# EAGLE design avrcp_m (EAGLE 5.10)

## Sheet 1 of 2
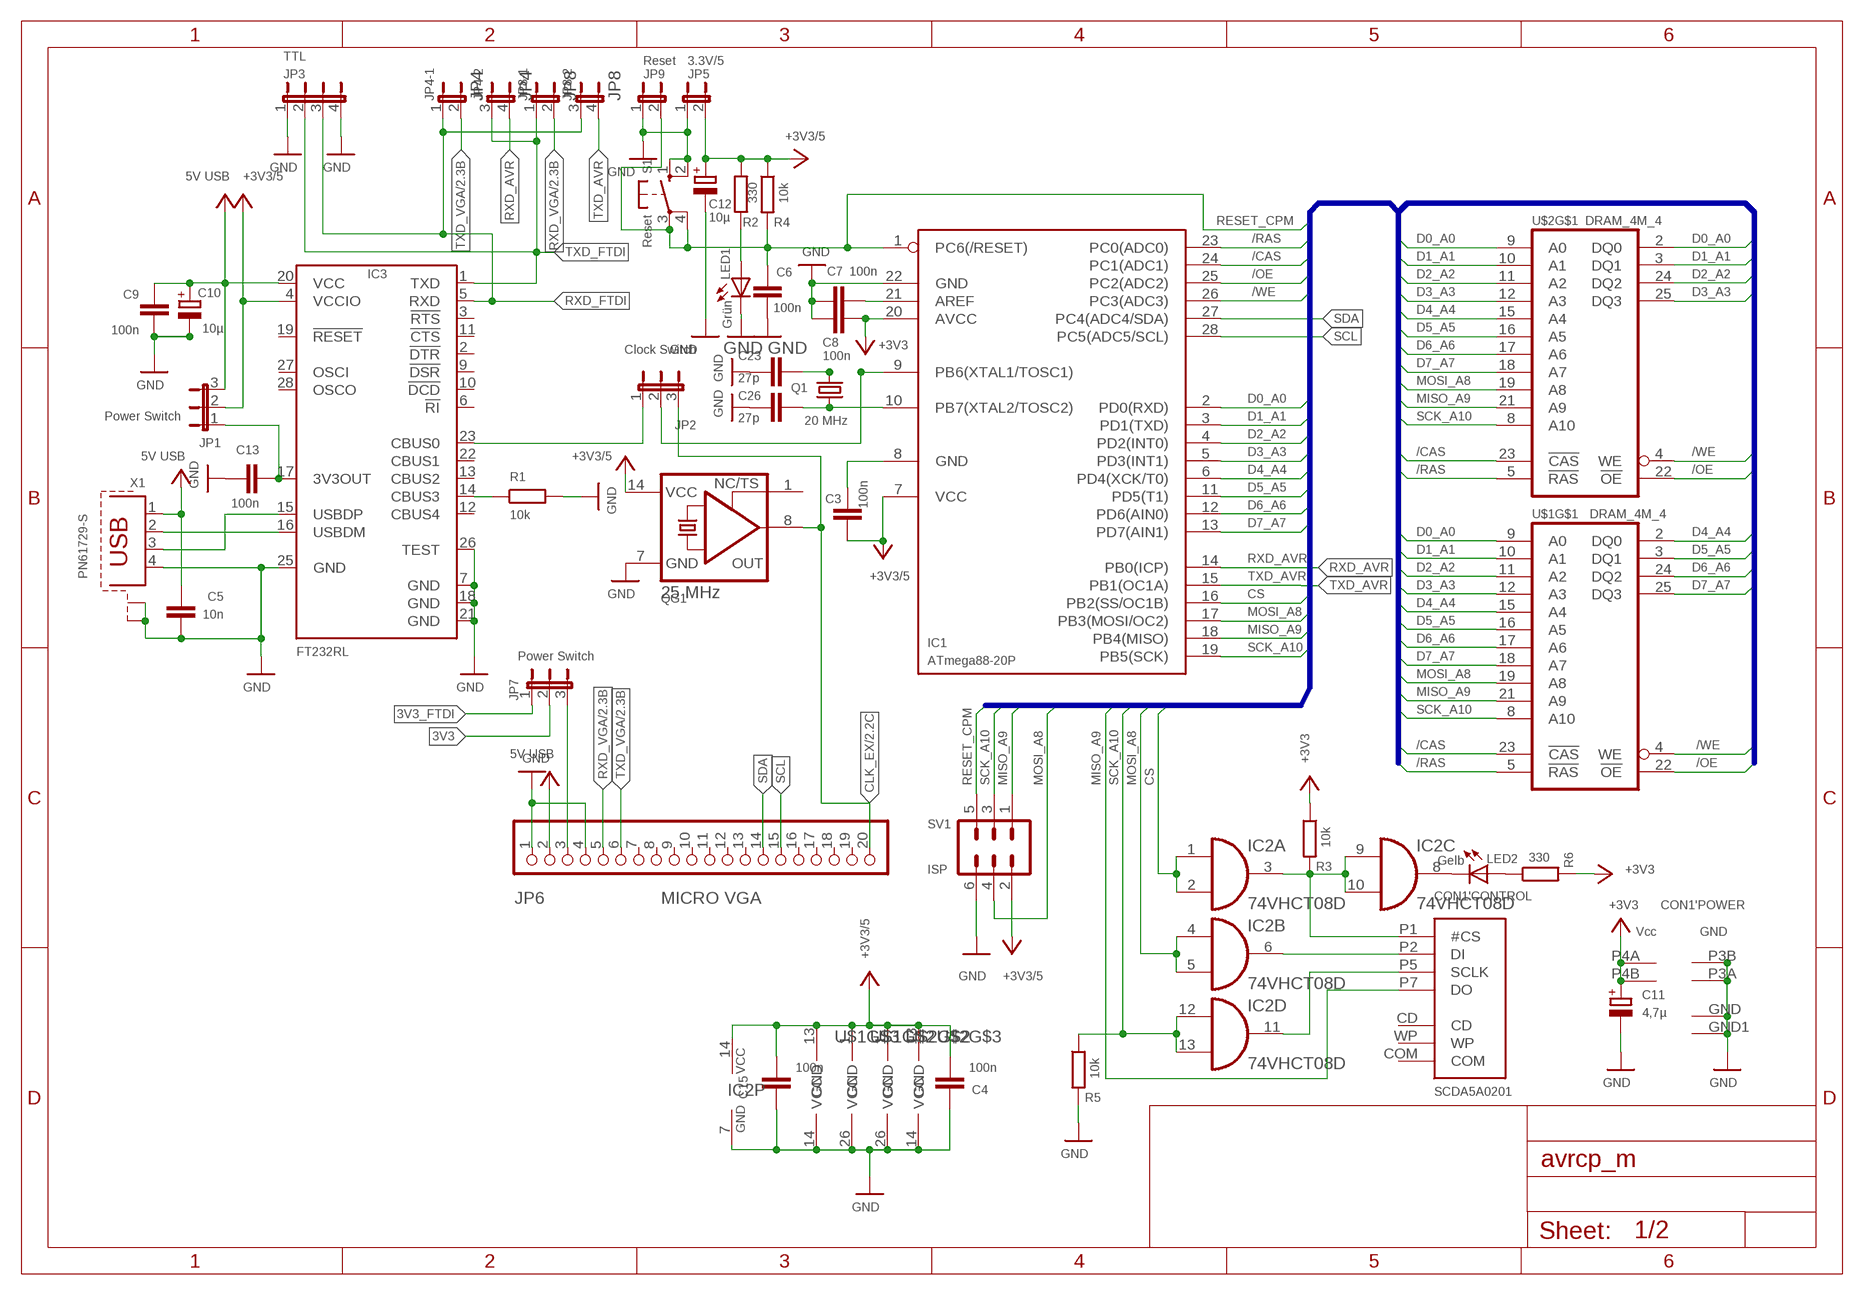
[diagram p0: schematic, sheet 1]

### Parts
C3  100n  C-EU025-024X044  [C025-024X044]
C4  100n  C-EU025-024X044  [C025-024X044]
C5  10n  C-EU025-024X044  [C025-024X044]
C6  100n  C-EU025-024X044  [C025-024X044]
C7  100n  C-EU025-024X044  [C025-024X044]
C8  100n  C-EU025-024X044  [C025-024X044]
C9  100n  C-EU025-024X044  [C025-024X044]
C10  10µ  CPOL-EUE2-5  [E2-5]
C11  4,7µ  CPOL-EUE2-4  [E2-4]
C12  10µ  CPOL-EUE2-4  [E2-4]
C13  100n  C-EU025-024X044  [C025-024X044]
C15  100n  C-EU025-024X044  [C025-024X044]
C23  27p  C-EU025-024X044  [C025-024X044]
C26  27p  C-EU025-024X044  [C025-024X044]
CON1  SCDA5A0201  [SCDA5A0201]
IC1  ATmega88-20P  MEGA8-P  [DIL28-3]
IC2  74VHCT08D  74S08D  [SO14]
IC3  FT232RL  [SSOP28]
JP1  Power Switch  JP2E  [JP2]
JP2  Clock Switch  JP2E  [JP2]
JP3  TTL  JP4E  [JP4]
JP4  JP4  JP2QE  [JP2Q]
JP5  3.3V/5  JP1E  [JP1]
JP6  MICRO VGA  PINHD-1X20  [1X20]
JP7  Power Switch  JP2E  [JP2]
JP8  JP8  JP2QE  [JP2Q]
JP9  Reset  JP1E  [JP1]
LED1  Grün  LED3MM  [LED3MM]
LED2  Gelb  LED3MM  [LED3MM]
Q1  20 MHz  CRYSTALHC49S  [HC49/S]
QG1  25 MHz  XO-14  [DIL14S]
R1  10k  R-EU_0207/7  [0207/7]
R2  330  R-EU_0207/7  [0207/7]
R3  10k  R-EU_M1206  [M1206]
R4  10k  R-EU_0207/7  [0207/7]
R5  10k  R-EU_M1206  [M1206]
R6  330  R-EU_0204/7  [0204/7]
S1  Reset  10-XX  [B3F-10XX]
SV1  ISP  ML6  [ML6]
U$1  DRAM_4M_4  [SOJ26-24]
U$2  DRAM_4M_4  [SOJ26-24]
X1  PN61729-S  [PN61729-S]

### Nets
3V3: C11.+ CON1.P4A('POWER:VCC) CON1.P4B('POWER:VCC1) JP7.2 R3.1 R6.2 ; supply symbol labelled +3V3
3V3_FTDI: C13.2 IC3.17(3V3OUT) JP1.1 JP7.1
3V3_VGA: JP6.3 JP7.3 ; also sheet 2
5V_USB: C5.2 C9.2 C10.+ IC3.20(VCC) JP1.3 JP6.2 X1.1 ; supply symbol labelled 5V USB ; also sheet 2
+3V3/5: C3.1 C4.2 C8.1 C12.+ C15.2 IC1.7(VCC) IC1.20(AVCC) IC2.14(P:VCC) IC3.4(VCCIO) JP1.2 JP5.2 QG1.14(VCC) R2.2 R4.1 SV1.2 U$1.1(VCC) U$1.13(VCC) U$2.1(VCC) U$2.13(VCC) ; supply symbol labelled +3V3
/CAS: IC1.24(PC1(ADC1)) U$1.23(!CAS) U$2.23(!CAS)
/OE: IC1.25(PC2(ADC2)) U$1.22(!OE) U$2.22(!OE)
/RAS: IC1.23(PC0(ADC0)) U$1.5(!RAS) U$2.5(!RAS)
/WE: IC1.26(PC3(ADC3)) U$1.4(WE) U$2.4(WE)
CLK_EX: JP2.3 JP6.20 QG1.8(OUT) ; also sheet 2
CS: IC1.16(PB2(SS/OC1B)) IC2.1(A:I0) IC2.2(A:I1)
CS_MMC: CON1.P1('CONTROL:#CS) IC2.3(A:O) IC2.9(C:I0) IC2.10(C:I1) R3.2
D0_A0: IC1.2(PD0(RXD)) U$1.9(A0) U$2.2(DQ0) U$2.9(A0)
D1_A1: IC1.3(PD1(TXD)) U$1.10(A1) U$2.3(DQ1) U$2.10(A1)
D2_A2: IC1.4(PD2(INT0)) U$1.11(A2) U$2.11(A2) U$2.24(DQ2)
D3_A3: IC1.5(PD3(INT1)) U$1.12(A3) U$2.12(A3) U$2.25(DQ3)
D4_A4: IC1.6(PD4(XCK/T0)) U$1.2(DQ0) U$1.15(A4) U$2.15(A4)
D5_A5: IC1.11(PD5(T1)) U$1.3(DQ1) U$1.16(A5) U$2.16(A5)
D6_A6: IC1.12(PD6(AIN0)) U$1.17(A6) U$1.24(DQ2) U$2.17(A6)
D7_A7: IC1.13(PD7(AIN1)) U$1.18(A7) U$1.25(DQ3) U$2.18(A7)
GND: C4.1 C5.1 C6.1 C7.2 C8.2 C9.1 C10.- C11.- C12.- C13.1 C15.1 C23.2 C26.2 CON1.GND1('POWER:GND) CON1.GND('POWER:GND) CON1.P3A('POWER:GND) CON1.P3B('POWER:GND) IC1.22(GND) IC2.7(P:GND) IC3.7(GND) IC3.18(GND) IC3.21(GND) IC3.25(GND) IC3.26(TEST) JP3.1 JP3.4 JP5.1 JP6.1 JP6.4 JP9.1 LED1.K(C) QG1.7(GND) R1.2 R5.2 S1.1(S) S1.2(S1) SV1.6 U$1.14(GND) U$1.26(GND) U$2.14(GND) U$2.26(GND) X1.4 X1.S1 X1.S2 ; also sheet 2
MISO_A9: CON1.P7('CONTROL:DO) IC1.18(PB4(MISO)) SV1.1 U$1.21(A9) U$2.21(A9)
MOSI_A8: IC1.17(PB3(MOSI/OC2)) IC2.4(B:I0) IC2.5(B:I1) SV1.4 U$1.19(A8) U$2.19(A8)
MOSI_MMC: CON1.P2('CONTROL:DI) IC2.6(B:O)
N$1: IC3.14(CBUS3) R1.1
N$3: C7.1 IC1.21(AREF)
N$4: IC1.9(PB6(XTAL1/TOSC1)) JP2.2
N$7: LED1.A R2.1
N$8: IC3.23(CBUS0) JP2.1
N$9: IC3.16(USBDM) X1.2
N$10: IC3.15(USBDP) X1.3
N$12: IC2.8(C:O) LED2.K(C)
N$13: LED2.A R6.1
N$14: C3.2 IC1.8(GND)
N$23: C26.1 IC1.10(PB7(XTAL2/TOSC2)) Q1.1
N$24: C23.1 Q1.2
RESET_CPM: C6.2 IC1.1(PC6(/RESET)) JP9.2 R4.2 S1.3(P) S1.4(P1) SV1.5
RXD_AVR: IC1.14(PB0(ICP)) JP4.4
RXD_FTDI: IC3.5(RXD) JP3.3 JP4.1 JP8.3
RXD_VGA: JP6.5 JP8.2 ; also sheet 2
SCK_A10: IC1.19(PB5(SCK)) IC2.12(D:I0) IC2.13(D:I1) R5.1 SV1.3 U$1.8(A10) U$2.8(A10)
SCK_MMC: CON1.P5('CONTROL:SCLK) IC2.11(D:O)
SCL: IC1.28(PC5(ADC5/SCL)) JP6.15
SDA: IC1.27(PC4(ADC4/SDA)) JP6.14
TXD_AVR: IC1.15(PB1(OC1A)) JP8.4
TXD_FTDI: IC3.1(TXD) JP3.2 JP4.3 JP8.1
TXD_VGA: JP4.2 JP6.6 ; also sheet 2
Unconnected: CON1.CD('CONTROL:CD) CON1.COM('CONTROL:COM) CON1.WP('CONTROL:WP) IC3.2(!DTR) IC3.3(!RTS) IC3.6(!RI) IC3.9(!DSR) IC3.10(!DCD) IC3.11(!CTS) IC3.12(CBUS4) IC3.13(CBUS2) IC3.19(!RESET) IC3.22(CBUS1) IC3.27(OSCI) IC3.28(OSCO) JP6.7 JP6.8 JP6.9 JP6.10 JP6.11 JP6.12 JP6.13 JP6.16 JP6.17 JP6.18 JP6.19 QG1.1(TS)

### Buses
SCK_A10,MISO_A9,MOSI_A8,D7_A7,D6_A6,D5_A5,D4_A4,D3_A3,D2_A2,D1_A1,D0_A0,/WE,/OE,/RAS,/CAS,RESET_CPM,CS,SCK

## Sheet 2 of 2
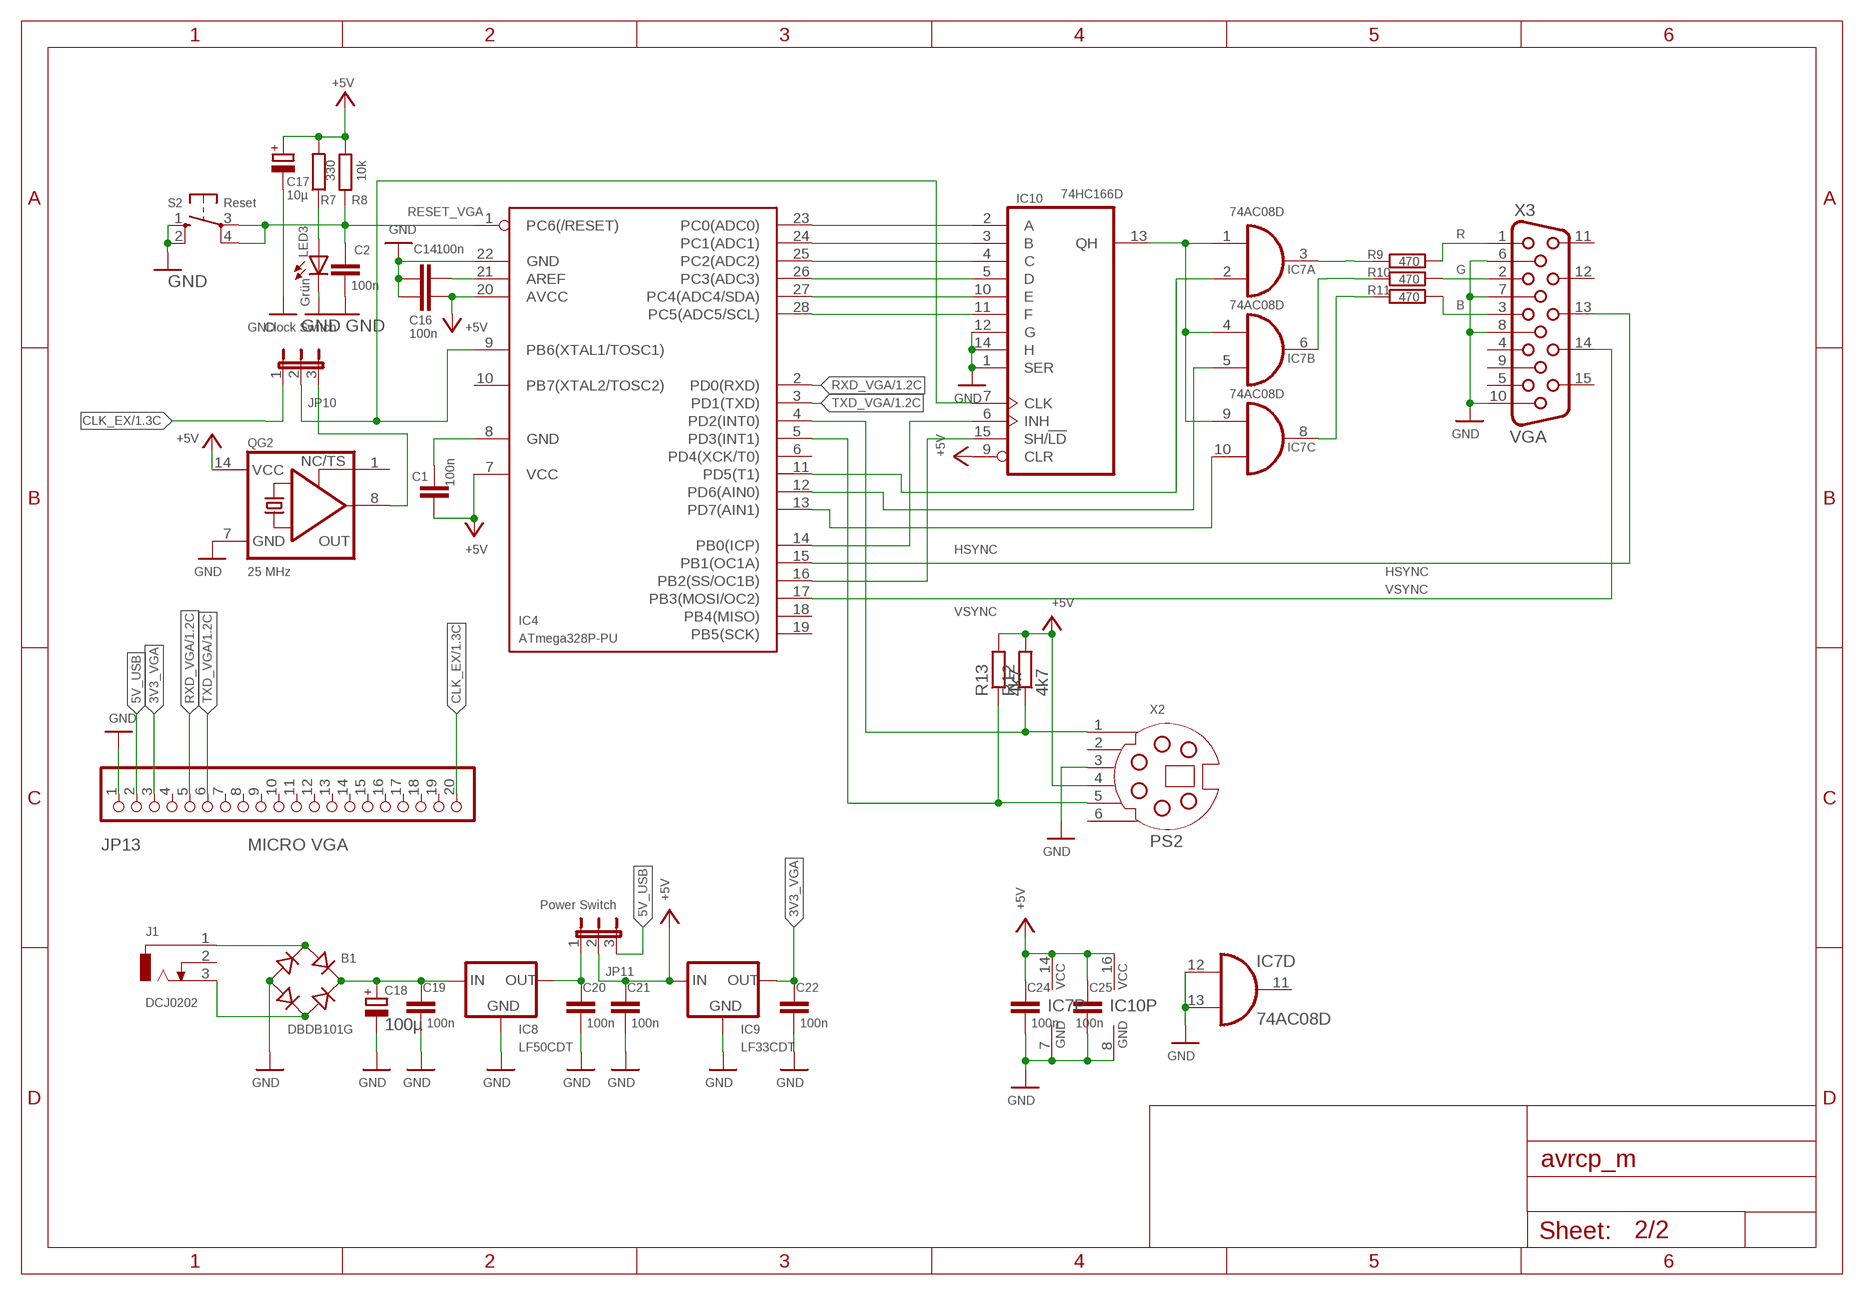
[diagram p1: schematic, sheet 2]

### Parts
B1  DBDB101G  [DB]
C1  100n  C-EUC0805  [C0805]
C2  100n  C-EUC0805  [C0805]
C14  100n  C-EUC0805  [C0805]
C16  100n  C-EUC0805  [C0805]
C17  10µ  CPOL-EUE2-4  [E2-4]
C18  100µ  CPOL-EUE2.5-6  [E2,5-6]
C19  100n  C-EUC0805  [C0805]
C20  100n  C-EUC0805  [C0805]
C21  100n  C-EUC0805  [C0805]
C22  100n  C-EUC0805  [C0805]
C24  100n  C-EUC0805  [C0805]
C25  100n  C-EUC0805  [C0805]
IC4  ATmega328P-PU  MEGA8-P  [DIL28-3]
IC7  74AC08D  [SO14]
IC8  LF50CDT  LP2950CDT-5.0  [DPACK]
IC9  LF33CDT  LP2950CDT-3.3  [DPACK]
IC10  74HC166D  [SO16]
J1  DCJ0202  [DCJ0202]
JP10  Clock Switch  JP2E  [JP2]
JP11  Power Switch  JP2E  [JP2]
JP13  MICRO VGA  PINHD-1X20  [1X20]
LED3  Grün  LED3MM  [LED3MM]
QG2  25 MHz  XO-14  [DIL14S]
R7  330  R-EU_M1206  [M1206]
R8  10k  R-EU_M1206  [M1206]
R9  470  R-EU_M1206  [M1206]
R10  470  R-EU_M1206  [M1206]
R11  470  R-EU_M1206  [M1206]
R12  4k7  R-EU_M1206  [M1206]
R13  4k7  R-EU_M1206  [M1206]
S2  Reset  10-XX  [B3F-10XX]
X2  PS2  MDSSV-BC06  [SSV-BC06]
X3  VGA  HF15H  [HDF15H]

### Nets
3V3_VGA: C22.2 IC9.3(OUT) JP13.3 ; also sheet 1
5V_USB: JP11.3 JP13.2 ; also sheet 1
+5V: C1.1 C16.1 C17.+ C21.2 C24.2 C25.2 IC4.7(VCC) IC4.20(AVCC) IC7.14(P:VCC) IC9.1(IN) IC10.9(CLR) IC10.16(VCC) JP11.2 QG2.14(VCC) R7.2 R8.1 R12.2 R13.2 X2.4
B: R11.2 X3.3
CLK: IC4.9(PB6(XTAL1/TOSC1)) IC10.7(CLK) JP10.2
CLK_EX: JP10.1 JP13.20 ; also sheet 1
G: R10.2 X3.2
GND: B1.- C2.1 C14.2 C16.2 C17.- C18.- C19.1 C20.1 C21.1 C22.1 C24.1 C25.1 IC4.22(GND) IC7.7(P:GND) IC7.12(D:I0) IC7.13(D:I1) IC8.4(GND) IC9.4(GND) IC10.1(SER) IC10.8(GND) IC10.12(G) IC10.14(H) JP13.1 LED3.K(C) QG2.7(GND) S2.1(S) S2.2(S1) X2.3 X3.6 X3.7 X3.8 X3.10 ; also sheet 1
HSYNC: IC4.15(PB1(OC1A)) X3.13
N$2: LED3.A R7.1
N$5: C14.1 IC4.21(AREF)
N$6: C1.2 IC4.8(GND)
N$11: IC4.23(PC0(ADC0)) IC10.2(A)
N$15: JP10.3 QG2.8(OUT)
N$16: IC4.24(PC1(ADC1)) IC10.3(B)
N$17: IC4.25(PC2(ADC2)) IC10.4(C)
N$18: IC4.26(PC3(ADC3)) IC10.5(D)
N$19: IC4.27(PC4(ADC4/SDA)) IC10.10(E)
N$20: IC4.28(PC5(ADC5/SCL)) IC10.11(F)
N$21: IC4.14(PB0(ICP)) IC10.6(INH)
N$22: IC4.16(PB2(SS/OC1B)) IC10.15(SH/!LD)
N$25: IC7.8(C:O) R11.1
N$26: IC7.1(A:I0) IC7.4(B:I0) IC7.9(C:I0) IC10.13(QH)
N$27: IC4.13(PD7(AIN1)) IC7.10(C:I1)
N$28: IC4.12(PD6(AIN0)) IC7.5(B:I1)
N$29: IC4.11(PD5(T1)) IC7.2(A:I1)
N$30: IC7.3(A:O) R9.1
N$31: IC7.6(B:O) R10.1
N$35: IC4.4(PD2(INT0)) R12.1 X2.1
N$36: IC4.5(PD3(INT1)) R13.1 X2.5
N$37: B1.AC1 J1.1
N$38: B1.AC2 J1.3
N$39: B1.+ C18.+ C19.2 IC8.1(IN)
N$40: C20.2 IC8.3(OUT) JP11.1
R: R9.2 X3.1
RESET_VGA: C2.2 IC4.1(PC6(/RESET)) R8.2 S2.3(P) S2.4(P1)
RXD_VGA: IC4.2(PD0(RXD)) JP13.5 ; also sheet 1
TXD_VGA: IC4.3(PD1(TXD)) JP13.6 ; also sheet 1
VSYNC: IC4.17(PB3(MOSI/OC2)) X3.14
Unconnected: IC4.6(PD4(XCK/T0)) IC4.10(PB7(XTAL2/TOSC2)) IC4.18(PB4(MISO)) IC4.19(PB5(SCK)) IC7.11(D:O) J1.2 JP13.4 JP13.7 JP13.8 JP13.9 JP13.10 JP13.11 JP13.12 JP13.13 JP13.14 JP13.15 JP13.16 JP13.17 JP13.18 JP13.19 QG2.1(TS) X2.2 X2.6 X3.4 X3.5 X3.9 X3.11 X3.12 X3.15

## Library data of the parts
B1 = rectifier:DB?*G: Single Phase 1.0 AMP Glass Passivated Bridge Rectifier Taiwan Semiconductor Co.,Ltd. - TSC Source: http://www.taiwansemi.com/TSCbig5/ezcatfiles/cust/img/img/db101g.pdf http://www.ts.com.tw/db/pictures/modules/PDT/PDT060207001/DBLS201G.pdf
C1-C9 C13-C16 C19-C26 = rcl:C-EU: CAPACITOR, European symbol
C10-C12 C17 C18 = rcl:CPOL-EU: POLARIZED CAPACITOR, European symbol
CON1 = SCDA5A0201:SCDA5A0201: ALPS Connector for SDMemory Card SD-CARD SCDA5A0201 SPI -MODE
IC1 IC4 = atmel:MEGA8-P: MICROCONTROLLER 8 Kbytes FLASH, 1 kbytes SRAM, 512 bytes EEPROM, USART, 4-channel 10 bit ADC, 2-channel 8 bit ADC Pin compatible with Atmega48, ATMega88, ATMega168 Source: avr.lbr
IC2 IC7 = 74xx-eu:74*08: Quad 2-input AND gate
IC3 = ftdichip:FT232R: Source: http://www.ftdichip.com/Documents/DataSheets/DS_FT232R_v104.pdf
IC8 IC9 = v-reg:LP2950?*: Source: http://cache.national.com/ds/LP/LP2950.pdf
IC10 = 74xx-eu:74*166: 8-bit parallel load SHIFT REGISTER
J1 = con-jack:DCJ0202: DC POWER JACK Source: DCJ0202.pdf
JP1 JP2 JP7 JP10 JP11 = jumper:JP2E: JUMPER
JP3 = jumper:JP4E: JUMPER
JP4 JP8 = jumper:JP2QE: JUMPER
JP5 JP9 = jumper:JP1E: JUMPER
JP6 JP13 = pinhead:PINHD-1X20: PIN HEADER
LED1-LED3 = led:LED: LED
Q1 = crystal:CRYSTAL: CRYSTAL
QG1 QG2 = crystal:XO-: CRYSTAL
R1-R13 = rcl:R-EU_: RESISTOR, European symbol
S1 S2 = switch-omron:10-XX: OMRON SWITCH
SV1 = con-harting-ml:ML6: HARTING
U$1 U$2 = AMESYS:DRAM_4M_4
X1 = con-berg:PN61729-S: BERG USB connector
X2 = con-yamaichi:MDSSV-BC06: YAMAICHI CONNECTOR
X3 = con-subd:HF15: SUB-D

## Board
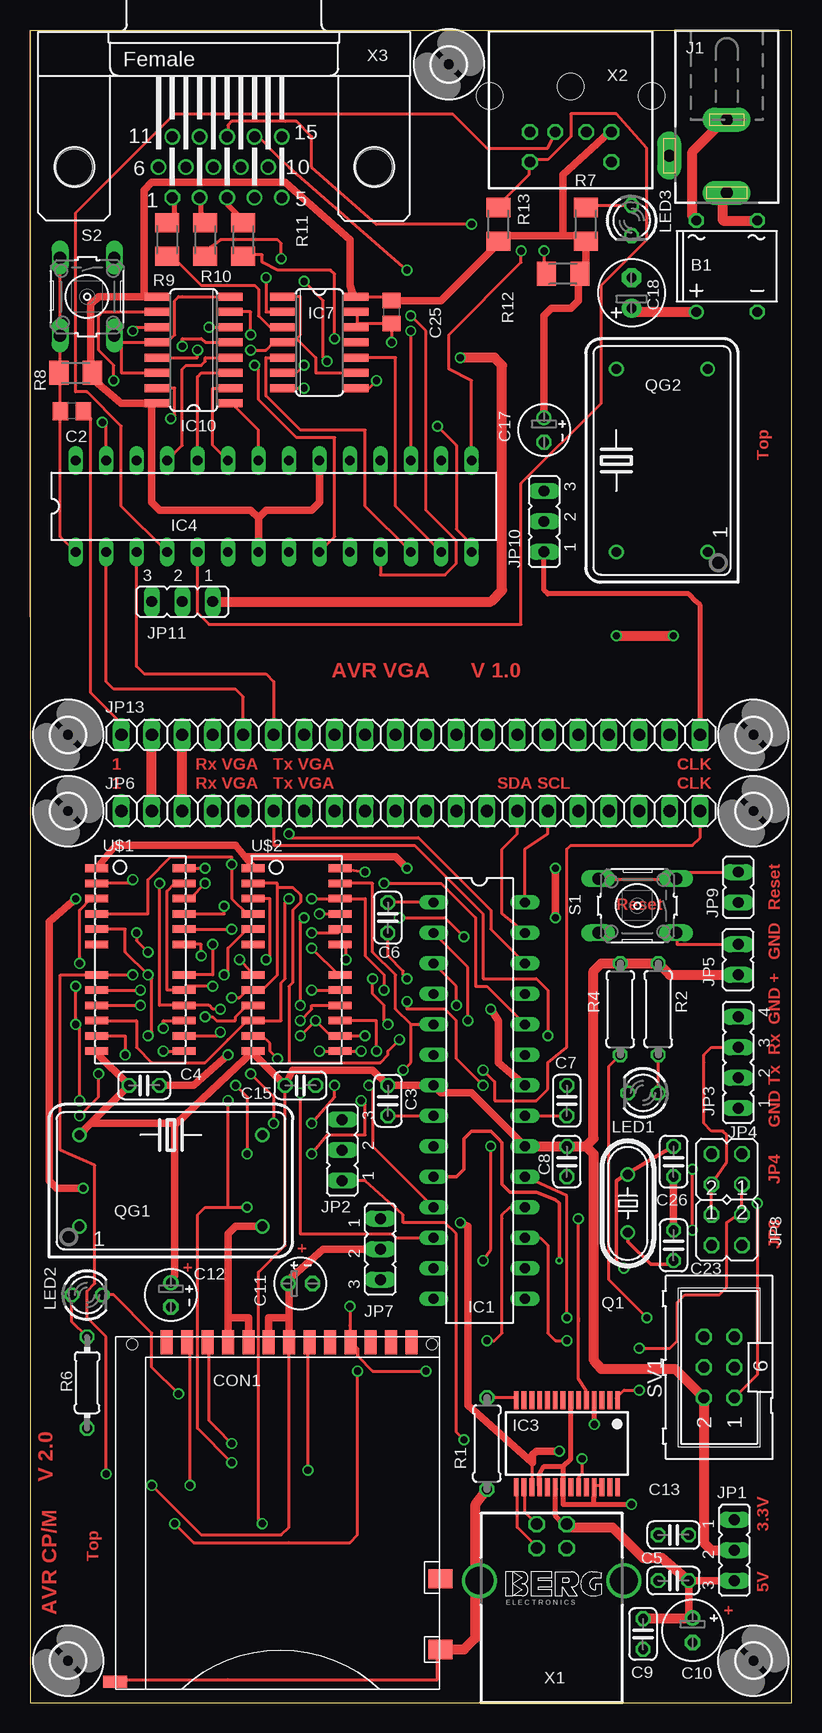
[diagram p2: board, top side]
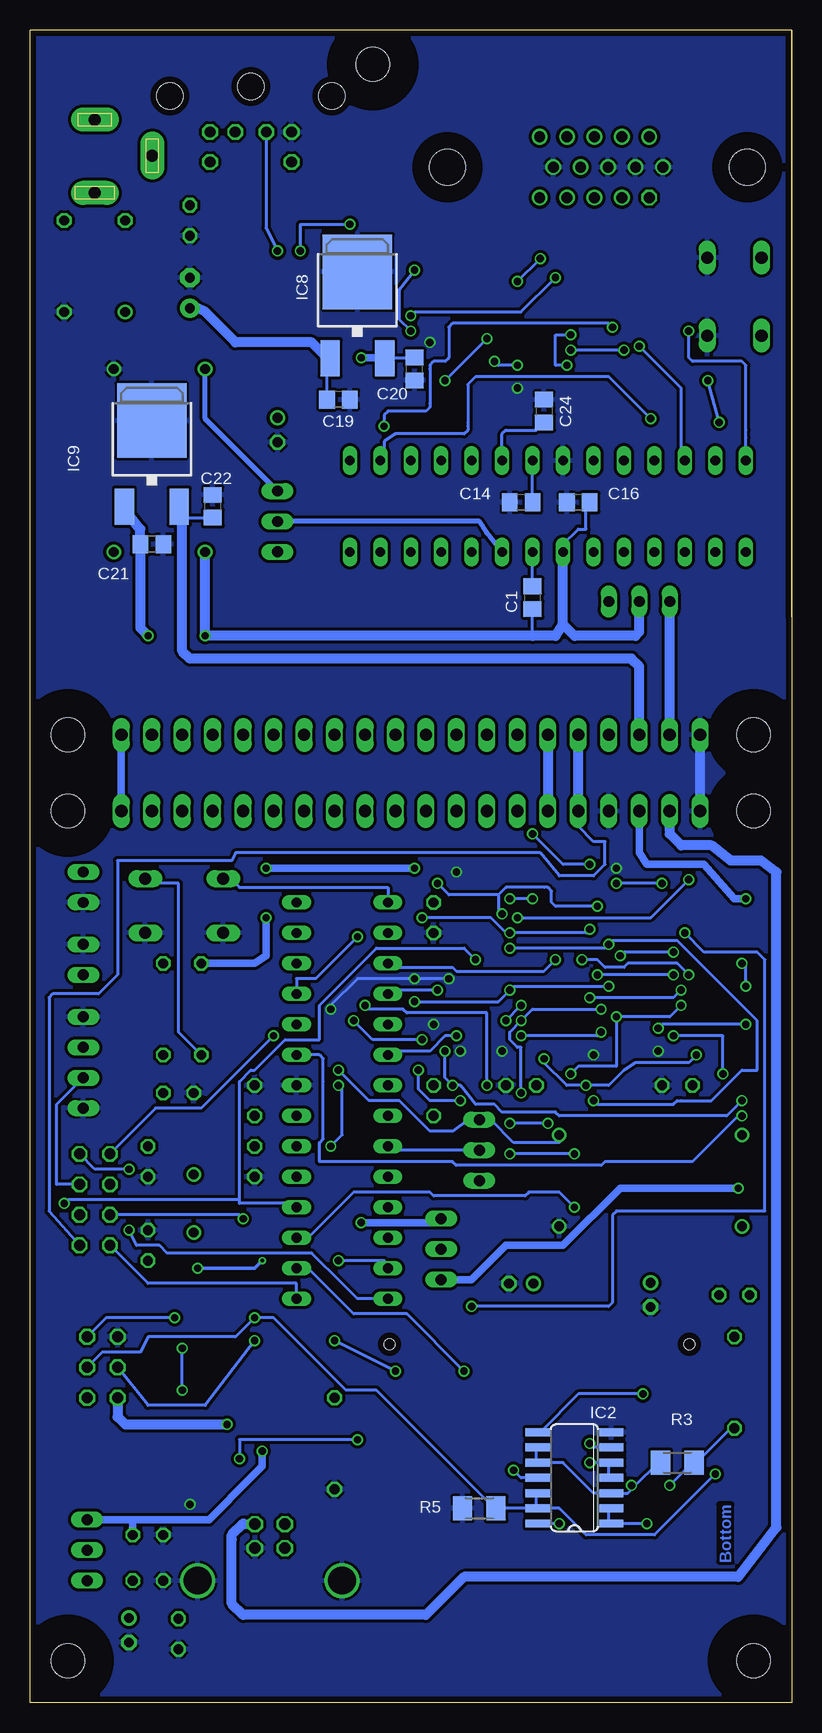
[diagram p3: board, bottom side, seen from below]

Size 63.5 x 139.38 mm. Coordinates in mm from the lower left corner, seen from the top.
Outline: 0,90.48 0,139.38
Outline: 0,139.38 0,90.48
Outline: 0,90.48 0,77.47 0,0 63.5,0 63.5,77.47 63.5,139.38 0,139.38
Copper layers (1*16): Top 0.035mm / dielectric 1.5mm / Bottom 0.035mm
Design rules "Eagle-DRU - 1109 - LeitOn - 01 and 02 layers": minimum track width 6mil, minimum drill 0.3mm, track to track 6mil, track to pad 6mil, pad to pad 6mil, via to via 6mil, smd to smd 6mil, copper to edge 20mil, drill to drill 10mil, minimum pad ring 8mil, minimum via ring 6mil, stop-mask expansion 3mil, vias tented up to drill 0mil, thermal gap 8mil

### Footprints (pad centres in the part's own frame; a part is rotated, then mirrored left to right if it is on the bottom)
DB = drill 0.813 round: + -2.54,-3.81 | drill 0.813 octagon: - 2.54,-3.81; AC1 2.54,3.81; AC2 -2.54,3.81
C0805 = smd 1.3 x 1.5: 1 -0.95,0; 2 0.95,0
C025-024X044 = drill 0.813 octagon: 1 -1.27,0; 2 1.27,0
E2-5 = drill 0.813 pad 1.27 round: + -1.016,0 | drill 0.813 pad 1.27 octagon: - 1.016,0
E2-4 = drill 0.813 pad 1.27 round: + -1.016,0 | drill 0.813 pad 1.27 octagon: - 1.016,0
E2,5-6 = drill 0.813 pad 1.6 round: + -1.27,0 | drill 0.813 pad 1.6 octagon: - 1.27,0
SCDA5A0201 = smd 1 x 2: CD 9.475,-0.45; COM 11.175,-0.45; P1 -7.525,-0.45; P2 -5.825,-0.45; P3A -4.125,-0.45; P3B -2.425,-0.45; P4A -0.725,-0.45; P4B 0.975,-0.45; P5 2.675,-0.45; P6 4.375,-0.45; P7 6.075,-0.45; P8 7.775,-0.45; P9 -9.225,-0.45 | smd 2 x 1.6: GND 13.575,-26.05; WP 13.575,-20.15 | smd 2 x 1: GND1 -13.525,-28.75 | hole 0.9: -12.125,-0.6; 12.875,-0.6
DIL28-3 = drill 0.813 long: 1 -16.51,-3.81; 2 -13.97,-3.81; 3 -11.43,-3.81; 4 -8.89,-3.81; 5 -6.35,-3.81; 6 -3.81,-3.81; 7 -1.27,-3.81; 8 1.27,-3.81; 9 3.81,-3.81; 10 6.35,-3.81; 11 8.89,-3.81; 12 11.43,-3.81; 13 13.97,-3.81; 14 16.51,-3.81; 15 16.51,3.81; 16 13.97,3.81; 17 11.43,3.81; 18 8.89,3.81; 19 6.35,3.81; 20 3.81,3.81; 21 1.27,3.81; 22 -1.27,3.81; 23 -3.81,3.81; 24 -6.35,3.81; 25 -8.89,3.81; 26 -11.43,3.81; 27 -13.97,3.81; 28 -16.51,3.81
SO14 = smd 0.66 x 2.032: 1 -3.81,-3.073; 2 -2.54,-3.073; 3 -1.27,-3.073; 4 0,-3.073; 5 1.27,-3.073; 6 2.54,-3.073; 7 3.81,-3.073; 8 3.81,3.073; 9 2.54,3.073; 10 1.27,3.073; 11 0,3.073; 12 -1.27,3.073; 13 -2.54,3.073; 14 -3.81,3.073
SSOP28 = smd 0.4 x 1.5: 1 -4.225,-3.625; 2 -3.575,-3.625; 3 -2.925,-3.625; 4 -2.275,-3.625; 5 -1.625,-3.625; 6 -0.975,-3.625; 7 -0.325,-3.625; 8 0.325,-3.625; 9 0.975,-3.625; 10 1.625,-3.625; 11 2.275,-3.625; 12 2.925,-3.625; 13 3.575,-3.625; 14 4.225,-3.625; 15 4.225,3.625; 16 3.575,3.625; 17 2.925,3.625; 18 2.275,3.625; 19 1.625,3.625; 20 0.975,3.625; 21 0.325,3.625; 22 -0.325,3.625; 23 -0.975,3.625; 24 -1.625,3.625; 25 -2.275,3.625; 26 -2.925,3.625; 27 -3.575,3.625; 28 -4.225,3.625
DPACK = smd 1.6 x 3: 1 -2.28,-4.8; 3 2.28,-4.8 | smd 5.8 x 6.2: 4 0,2.38
SO16 = smd 0.66 x 2.032: 1 -4.445,-3.073; 2 -3.175,-3.073; 3 -1.905,-3.073; 4 -0.635,-3.073; 5 0.635,-3.073; 6 1.905,-3.073; 7 3.175,-3.073; 8 4.445,-3.073; 9 4.445,3.073; 10 3.175,3.073; 11 1.905,3.073; 12 0.635,3.073; 13 -0.635,3.073; 14 -1.905,3.073; 15 -3.175,3.073; 16 -4.445,3.073
DCJ0202 = drill 1 pad 2 long: 1 0,3.1; 2 4.8,0; 3 0,-3
JP2 = drill 0.914 long: 1 -2.54,0; 2 0,0; 3 2.54,0
JP4 = drill 0.914 long: 1 -3.81,0; 2 -1.27,0; 3 1.27,0; 4 3.81,0
JP2Q = drill 0.914 octagon: 1 -1.27,-1.27; 2 -1.27,1.27; 3 1.27,-1.27; 4 1.27,1.27
JP1 = drill 0.914 long: 1 0,-1.27; 2 0,1.27
1X20 = drill 1.016 long: 1 -24.13,0; 2 -21.59,0; 3 -19.05,0; 4 -16.51,0; 5 -13.97,0; 6 -11.43,0; 7 -8.89,0; 8 -6.35,0; 9 -3.81,0; 10 -1.27,0; 11 1.27,0; 12 3.81,0; 13 6.35,0; 14 8.89,0; 15 11.43,0; 16 13.97,0; 17 16.51,0; 18 19.05,0; 19 21.59,0; 20 24.13,0
LED3MM = drill 0.813 octagon: A -1.27,0; K 1.27,0
HC49/S = drill 0.813 round: 1 -2.413,0; 2 2.413,0
DIL14S = drill 0.813 round: 1 -7.62,-3.81; 7 7.62,-3.81; 8 7.62,3.81; 14 -7.62,3.81
0207/7 = drill 0.813 octagon: 1 -3.81,0; 2 3.81,0
M1206 = smd 1.6 x 2: 1 -1.4,0; 2 1.4,0
0204/7 = drill 0.813 octagon: 1 -3.81,0; 2 3.81,0
B3F-10XX = drill 1.016 long: 1 -3.251,2.261; 2 3.251,2.261; 3 -3.251,-2.261; 4 3.251,-2.261
ML6 = drill 0.914 octagon: 1 -2.54,-1.27; 2 -2.54,1.27; 3 0,-1.27; 4 0,1.27; 5 2.54,-1.27; 6 2.54,1.27
SOJ26-24 = smd 0.635 x 1.905: 1 -7.62,-3.632; 2 -6.35,-3.632; 3 -5.08,-3.632; 4 -3.81,-3.632; 5 -2.54,-3.632; 6 -1.27,-3.632; 8 1.27,-3.632; 9 2.54,-3.632; 10 3.81,-3.632; 11 5.08,-3.632; 12 6.35,-3.632; 13 7.62,-3.632; 14 7.62,3.632; 15 6.35,3.632; 16 5.08,3.632; 17 3.81,3.632; 18 2.54,3.632; 19 1.27,3.632; 21 -1.27,3.632; 22 -2.54,3.632; 23 -3.81,3.632; 24 -5.08,3.632; 25 -6.35,3.632; 26 -7.62,3.632
2,8 = hole 2.8: 0,0
PN61729-S = drill 0.95 octagon: 1 1.25,4.71; 2 -1.25,4.71; 3 -1.25,2.71; 4 1.25,2.71 | drill 2.3 pad 2.9 round: S1 -6.02,0; S2 6.02,0
SSV-BC06 = drill 0.9 octagon: 1 1.3,8.5; 2 -1.3,8.5; 3 3.4,8.5; 4 -3.4,8.5; 5 3.4,11; 6 -3.4,11 | hole 2.2: -6.75,5.5; 0,4.7; 6.75,5.5
HDF15H = drill 0.9 octagon: 1 4.329,2.54 | drill 0.9 round: 2 2.043,2.54; 3 -0.243,2.54; 4 -2.529,2.54; 5 -4.815,2.54; 6 5.472,0; 7 3.186,0; 8 0.9,0; 9 -1.386,0; 10 -3.672,0; 11 4.329,-2.54; 12 2.043,-2.54; 13 -0.243,-2.54; 14 -2.529,-2.54; 15 -4.815,-2.54 | hole 3: -12.5,0; 12.5,0

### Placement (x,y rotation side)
B1  58.1,119.7 0 top
C1  21.59,92.08 90 bottom
C2  3.49,107.63 180 top
C3  29.84,50.16 270 top
C4  9.53,51.44 180 top
C5  53.66,10.16 0 top
C6  29.84,65.41 90 top
C7  44.77,50.16 90 top
C8  44.77,45.09 270 top
C9  51.12,5.71 90 top
C10  55.24,6.03 270 top
C11  22.54,34.92 0 top
C12  11.75,33.97 270 top
C13  53.66,13.97 0 top
C14  22.54,100.01 180 bottom
C15  22.54,51.44 180 top
C16  17.78,100.01 180 bottom
C17  42.86,106.05 270 top
C18  50.16,117.47 90 top
C19  37.78,108.58 180 bottom
C20  31.43,111.12 90 bottom
C21  53.34,96.52 180 bottom
C22  48.26,99.69 270 bottom
C23  53.66,38.1 90 top
C24  20.64,107.63 270 bottom
C25  30.16,115.89 90 top
C26  53.66,45.09 270 top
CON1  20.64,30.48 0 top
IC1  37.47,50.16 270 top
IC2  18.1,18.73 90 bottom
IC3  44.77,21.59 180 top
IC4  20.32,99.69 0 top
IC7  24.13,113.35 270 top
IC8  36.2,116.84 0 bottom
IC9  53.34,104.46 0 bottom
IC10  13.65,112.71 90 top
J1  58.1,128.91 180 top
JP1  58.74,12.7 270 top
JP2  26.04,46.04 90 top
JP3  59.05,53.34 90 top
JP4  58.1,44.45 0 top
JP5  59.05,61.91 180 top
JP6  31.75,74.3 0 top
JP7  29.21,37.78 270 top
JP8  58.1,39.37 180 top
JP9  59.05,67.94 0 top
JP10  42.86,98.42 90 top
JP11  12.7,91.76 180 top
JP13  31.75,80.64 0 top
LED1  51.12,50.8 180 top
LED2  4.76,33.97 0 top
LED3  50.16,123.51 270 top
Q1  49.85,41.59 270 top
QG1  11.75,43.5 0 top
QG2  52.7,103.5 90 top
R1  38.1,21.59 270 top
R2  52.39,57.78 90 top
R3  9.53,20 180 bottom
R4  49.21,57.78 270 top
R5  26.04,16.19 180 bottom
R6  4.76,26.67 270 top
R7  46.35,123.19 270 top
R8  3.81,110.81 180 top
R9  11.43,121.92 90 top
R10  14.61,121.92 90 top
R11  17.78,121.92 90 top
R12  44.45,119.06 0 top
R13  39.05,123.19 270 top
S1  50.64,66.41 180 top
S2  4.76,117.16 270 top
SV1  57.47,27.94 90 top
U$1  9.21,61.91 270 top
U$2  22.23,61.91 270 top
U$3  [2,8]  60.33,74.3 0 top
U$4  [2,8]  60.33,3.49 0 top
U$5  [2,8]  3.17,74.3 0 top
U$6  [2,8]  3.17,3.49 0 top
U$7  [2,8]  3.17,80.64 0 top
U$8  [2,8]  60.33,80.64 0 top
U$9  [2,8]  34.92,136.53 0 top
X1  43.5,10.16 0 top
X2  45.09,139.38 180 top
X3  16.19,127.95 180 top

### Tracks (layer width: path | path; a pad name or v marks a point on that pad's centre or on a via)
3V3  (via drill 0.61)
  Top 0.254: CON1.P4B 21.59,30.48 | CON1.P4B 21.59,32.07 | v10.16,18.1 14.29,13.97 20.95,13.97 21.59,14.61 21.59,29.84 CON1.P4B | 21.59,34.92 C11.+
  Top 0.61: 21.59,32.07 21.59,34.92 | 21.59,30.48 21.59,32.07 | 21.59,32.07 19.89,32.05 CON1.P4A | JP7.2 27.62,37.78 27.3,37.78 24.45,37.78 21.53,35.18 C11.+
  Bottom 0.254: R6.2 5.08,22.86 7.94,20 R3.1 8.26,20 v10.16,18.1
3V3_FTDI  (via drill 0.61)
  Top 0.254: 41.91,18.1 IC3.17 41.91,18.1 | 41.91,18.1 41.91,20 41.91,20.64
  Top 0.61: v44.13,20.95 42.23,20.95 41.91,20.64 41.91,20 36.51,24.77 36.51,39.69 v35.88,40.01
  Bottom 0.61: 54.93,15.24 C13.2 | 54.93,15.24 58.1,15.24 JP1.1 | v44.13,20.95 44.13,19.68 45.09,18.73 48.58,15.24 54.93,15.24 | JP7.1 29.53,40.01 v35.88,40.01
3V3_VGA  (via drill 0.61)
  Top 0.61: v4.45,42.86 2.22,42.86 1.59,43.5 1.59,43.81 1.59,65.09 v3.81,66.99
  Top 0.813: JP6.3 JP13.3
  Bottom 0.254: C22.2 50.8,98.74 IC9.3
  Bottom 0.61: JP7.3 26.67,35.24 23.81,38.1 19.05,38.1 14.29,42.86 v4.45,42.86 | v3.81,66.99 4.76,66.99 7.3,69.85 12.06,69.85 12.7,70.8 JP6.3 | 50.8,98.74 50.8,98.97 IC9.3
  Bottom 0.813: 50.8,98.74 50.8,87.63 50.16,87 13.34,87 12.7,86.36 JP13.3
5V_USB
  Top 0.254: 43.81,17.78 IC3.20 | X1.1 44.45,14.92 | 55.24,10.16 C5.2 54.93,9.84 | 54.93,7.3 C10.+
  Top 0.406: 43.81,17.78 43.81,15.56 44.45,14.92
  Top 0.61: 55.24,10.16 JP1.3 | 54.93,9.84 54.93,7.3
  Top 0.813: C5.2 52.7,12.06 51.75,12.06 51.12,12.06 49.85,13.34 48.58,14.61 45.01,14.61 X1.1 | 54.93,6.99 C9.2 54.93,6.99 | C10.+ 54.93,6.99 | JP6.2 JP13.2
  Bottom 0.254: 10.16,72.39 10.16,72.71
  Bottom 0.813: 10.16,72.39 9.21,71.44 6.67,71.44 5.08,70.17 2.54,70.17 1.27,69.22 1.27,14.61 4.45,10.48 27.3,10.48 30.48,7.3 45.72,7.3 46.67,8.26 46.67,13.58 46.67,13.97 45.72,14.92 X1.1 | 10.16,72.71 JP6.2 | JP13.2 JP11.3
+3V3/5  (via drill 0.6, 0.61)
  Top 0.254: IC3.4 46.99,25.08 47.06,25.08 | 11.75,35.24 C12.+ | v19.37,14.92 19.05,15.24 19.05,35.88 21.27,38.1 C15.2 | 18.1,70.48 18.57,69.69
  Top 0.406: v47.06,23.18 47.06,25.08
  Top 0.61: IC1.20 36.83,50.8 34.29,50.8 IC1.7 C3.1 28.57,52.7 21.91,52.7 C15.2 18.59,54.12 U$2.13 12.24,48.26 | 12.06,48.26 11.43,48.26 | 11.43,48.26 10.16,48.26 5.08,48.26 | 12.24,48.26 12.06,48.26 | 12.06,48.26 11.43,48.26 | 12.24,48.26 12.06,48.26 | 12.06,48.26 11.43,48.26 | 12.24,48.26 12.06,48.26 | 5.08,48.26 C4.2 | 5.08,48.26 C4.2 | 5.08,48.26 QG1.14 | C4.2 5.58,54.12 U$1.13 | U$1.1 7.16,71.44 17.14,71.44 18.57,69.69 18.59,69.67 U$2.1 | 12.06,48.26 12.06,35.56 11.75,35.24 | 18.1,70.48 23.18,70.48 24.77,70.48 30.48,70.48 v31.43,69.53 | v43.81,65.41 v43.81,69.53
  Top 0.813: JP5.2 53.34,60.64 R2.2 R4.1 47.62,61.59 46.99,60.96 46.99,46.99 46.35,46.35 | IC1.20 C8.1 46.35,46.35 | JP1.2 56.83,12.7 56.2,13.34 56.2,17.14 56.2,17.78 56.2,18.41 56.2,20.64 SV1.2 53.79,27.81 47.62,27.81 46.99,28.57 46.99,45.09 46.99,45.72 46.35,46.35
  Bottom 0.254: v19.37,14.92 20.95,14.92 IC2.14
  Bottom 0.61: v43.81,65.41 43.81,62.23 44.77,61.59 47.94,61.59 R4.1 | v43.81,69.53 43.18,69.53 v31.43,69.53
  Bottom 0.813: v47.06,23.18 54.61,23.18 55.56,23.18 56.2,23.81 SV1.2
+5V  (via drill 0.6)
  Top 0.254: R13.2 39.05,121.6 R13.2 | 46.35,119.38 46.04,119.06 R12.2 45.72,118.43 | R7.2 46.35,121.6 | 42.86,107.31 C17.+ | R13.2 39.05,122.24 | 48.26,130.81 X2.4 | C25.2 29.84,117.16 27.3,117.16 IC7.14 26.99,117.16 | C25.2 | 5.08,110.81 R8.1 5.4,110.81 5.4,110.17 | 9.53,117.16 10.48,117.16 IC10.9 9.53,117.16 | 10.16,108.27 10.48,108.27 IC10.16 10.16,108.27
  Top 0.61: 46.35,121.6 46.35,119.38 | 42.86,107.31 42.86,115.57 43.5,116.2 45.09,116.2 45.72,116.84 45.72,117.16 45.72,118.43 | 39.05,122.24 44.45,122.24 | 48.26,130.81 44.45,127.32 44.45,122.24 | C25.2 34.29,116.84 36.83,119.38 39.05,121.6 | 5.08,110.81 5.08,114.94 5.08,116.52 5.71,117.16 9.53,117.16 9.53,125.41 9.53,126.05 10.16,126.68 21.27,126.68 26.67,121.92 26.67,118.11 26.99,117.16 | R7.2 46.35,122.24 46.04,122.24 44.45,122.24 | 5.4,110.17 7.62,108.27 10.16,108.27 10.16,100.65 10.16,100.01 10.79,99.38 18.41,99.38 19.05,98.74 | IC4.7 19.05,98.74 | 19.05,98.74 19.68,99.38 23.5,99.38 24.13,100.01 24.13,101.28 IC4.20
  Top 0.813: v48.9,88.9 v53.66,88.9
  Bottom 0.254: 24.13,103.19 IC4.20 24.13,105.73 23.81,106.05 21.27,106.05 C24.2 | IC4.7 19.05,96.52 17.78,97.79 17.14,97.79 17.14,100.01 C16.1 | 55.56,99.38 IC9.1 | C21.2 | 21.59,88.9 C1.1
  Bottom 0.813: JP11.2 12.7,89.22 13.02,88.9 18.1,88.9 19.05,89.85 | 19.05,89.85 IC4.7 | C21.2 54.29,89.53 v53.66,88.9 | 19.05,89.85 19.68,88.9 21.59,88.9 v48.9,88.9 QG2.14 | 55.56,99.38 54.29,97.79 C21.2
/CAS  (via drill 0.61)
  Top 0.254: v16.19,66.36 16.19,65.72 13.02,65.72 U$1.23 | v24.13,65.72 25.72,65.72 U$2.23 | IC1.24 38.1,59.69 37.15,59.69 37.15,65.41 34.29,68.26 v29.53,68.26
  Bottom 0.254: v16.19,66.36 19.68,66.36 20,66.67 20,67.63 20.32,67.94 20.64,67.94 23.81,67.94 24.45,67.31 | 24.45,67.31 24.45,65.72 v24.13,65.72 | v29.53,68.26 28.57,67.31 24.45,67.31
/OE  (via drill 0.61)
  Top 0.254: v16.83,64.45 13.02,64.45 U$1.22 | v23.5,64.14 25.72,64.14 25.72,64.45 U$2.22 | v36.2,63.82 34.61,65.41 v30.8,65.41
  Bottom 0.254: v16.83,64.45 17.14,64.14 v23.5,64.14 23.81,64.14 25.08,65.41 v30.8,65.41 | IC1.25 41.27,60.33 39.69,60.33 v36.2,63.82
/RAS  (via drill 0.61)
  Top 0.254: v16.19,60.64 16.51,60.96 16.51,62.87 18.1,64.45 18.41,64.45 U$2.5 | U$1.5 5.71,64.45 7.94,64.45 7.94,62.55 v9.84,60.64 10.16,60.33 10.16,55.88 v9.84,55.56 | v4.13,48.9 5.71,50.48 v5.71,52.39
  Bottom 0.254: v9.84,60.64 v16.19,60.64 | IC1.23 39.37,53.98 39.05,53.66 39.05,51.75 39.05,46.99 39.37,46.67 39.37,45.09 28.26,45.09 27.94,44.77 15.88,44.77 15.56,45.09 8.26,45.09 4.45,48.9 v4.13,48.9 | v5.71,52.39 5.71,55.56 v9.84,55.56
/WE  (via drill 0.61)
  Top 0.254: U$1.4 5.71,65.72 9.84,65.72 9.84,68.58 11.75,70.48 16.83,70.48 v16.83,69.85 16.83,66.99 18.1,65.72 18.41,65.72 U$2.4 | IC1.26 38.42,64.45 38.42,66.04 32.38,72.07 21.59,72.07 v21.59,72.39
  Bottom 0.254: v21.59,72.39 19.05,69.85 v16.83,69.85
B
  Top 0.254: 17.46,123.83 R11.2 | 16.51,125.41 X3.3
  Top 0.406: 17.46,123.83 16.51,124.78 16.51,125.41
CLK  (via drill 0.61)
  Top 0.254: v18.41,113.98 18.41,115.89 16.83,115.89 IC10.7 | v18.73,111.44 19.05,111.12 19.05,108.58 22.23,105.41 25.4,105.41 25.4,97.16 IC4.9
  Bottom 0.254: v18.41,113.98 19.68,113.98 19.68,111.44 v18.73,111.44
  Bottom 0.406: IC4.9 25.4,97.47 26.04,98.42 42.55,98.42 JP10.2
CLK_EX  (via drill 0.61)
  Top 0.254: v37.78,52.7 38.73,51.75 38.73,50.16 42.23,50.16 43.18,51.12 43.18,53.34 44.77,54.61 44.77,70.17 44.77,71.12 45.09,71.44 47.62,71.44 55.24,71.44 55.88,72.07 JP6.20
  Top 0.406: JP10.1 42.86,92.71 43.18,92.39 54.93,92.39 55.56,91.76 55.88,91.44 JP13.20
  Bottom 0.254: QG1.8 19.37,46.67 23.18,46.67 25.08,48.58 JP2.3 26.99,48.58 28.26,47.62 30.16,47.62 32.7,50.16 35.24,50.16 v37.78,52.7
  Bottom 0.61: JP6.20 JP13.20
CS  (via drill 0.61)
  Top 0.254: v12.06,14.92 13.65,13.34 21.59,13.34 26.67,13.34 27.3,13.97 v27.3,27.62
  Bottom 0.254: IC2.2 15.24,16.19 15.24,14.92 IC2.1 14.92,14.92 v12.06,14.92 | v27.3,27.62 32.07,32.38 36.51,32.38 40.32,36.2 IC1.16
CS_MMC  (via drill 0.61)
  Top 0.254: v13.34,18.1 13.34,29.84 CON1.P1
  Bottom 0.254: IC2.9 21.27,21.27 21.27,20 IC2.10 20.95,20 19.05,20 16.51,17.46 15.24,17.46 IC2.3 14.92,17.46 13.65,17.46 13.02,18.1 | 13.02,18.1 11.11,20 R3.2 | 13.02,18.1 v13.34,18.1
D0_A0  (via drill 0.61)
  Top 0.254: v9.21,59.37 5.71,59.37 U$1.9 | v16.83,58.74 17.46,58.74 18.1,59.37 18.41,59.37 U$2.9 18.73,59.37 19.37,59.37 20.64,60.64 20.64,67.94 | 20.64,67.94 20.64,68.26 18.73,68.26 U$2.2 | IC1.2 36.51,61.28 v36.51,56.83 | v30.8,55.24 29.84,54.29 29.84,53.98 29.21,53.34 21.59,53.34 21.59,59.69 21.91,60.01 21.91,66.04 22.54,66.67 22.54,67.31 21.91,67.94 20.64,67.94
  Bottom 0.254: v9.21,59.37 9.84,58.74 v16.83,58.74 | v36.51,56.83 34.92,55.24 v30.8,55.24
D1_A1  (via drill 0.61)
  Top 0.254: v9.21,58.1 5.71,58.1 U$1.10 | v14.61,57.15 15.24,57.15 15.56,56.83 17.14,56.83 17.14,57.15 18.1,58.1 18.41,58.1 U$2.10 | v19.68,61.91 20,62.23 20,66.99 18.73,66.99 U$2.3 | v18.41,52.39 20.32,50.48 v20.32,48.26 | v23.5,48.26 25.4,50.48 v25.4,51.44 | v35.56,58.1 35.56,59.69 IC1.3
  Bottom 0.254: v9.21,58.1 10.16,57.15 v14.61,57.15 14.61,53.02 17.78,53.02 v18.41,52.39 | v19.68,61.91 20.64,60.96 27.94,60.96 28.26,61.28 33.34,61.28 IC1.3 | v20.32,48.26 v23.5,48.26 | v25.4,51.44 25.4,57.47 32.07,57.47 32.38,57.78 35.24,57.78 v35.56,58.1
D2_A2  (via drill 0.61)
  Top 0.254: U$1.11 5.71,56.83 8.89,56.83 8.89,54.61 10.16,53.34 14.61,53.34 16.51,55.24 18.1,56.83 18.41,56.83 U$2.11 18.73,56.83 20.95,56.83 20.95,60.01 21.27,60.33 21.27,66.67 v21.59,66.99 | v29.53,59.37 29.53,60.64 27.94,62.23 27.94,66.99 26.04,66.99 U$2.24 25.72,66.99 v23.5,66.99
  Bottom 0.254: v29.53,59.37 33.34,59.37 IC1.4 | v21.59,66.99 v23.5,66.99
D3_A3  (via drill 0.61)
  Top 0.254: v7.94,53.98 7.94,55.56 5.71,55.56 U$1.12 | v20.64,53.66 20,54.29 20,54.93 19.37,55.56 18.73,55.56 U$2.12 | 31.75,56.52 30.48,57.78 30.48,60.64 28.57,62.55 28.57,68.26 26.04,68.26 U$2.25 | 31.75,56.52 IC1.5 | v17.14,51.44 18.1,50.48 v18.1,45.72 | v23.5,45.72 24.77,47.31 27.94,47.31 27.94,49.85 v27.62,50.16 | v31.11,52.7 31.75,53.34 31.75,56.52
  Bottom 0.254: v7.94,53.98 8.57,53.34 13.02,53.34 13.97,52.7 15.24,51.44 v17.14,51.44 18.73,51.44 20.64,53.34 v20.64,53.66 | v18.1,45.72 18.41,45.72 v23.5,45.72 | v27.62,50.16 30.16,50.16 31.11,51.12 v31.11,52.7
D4_A4  (via drill 0.61)
  Top 0.254: v8.57,68.58 8.57,68.26 5.71,68.26 U$1.2 | v22.86,65.41 22.54,65.09 v22.54,58.1 | v15.88,55.88 15.88,55.56 13.02,55.56 U$1.15 | v22.54,55.56 v23.81,56.83 25.08,55.56 25.72,55.56 U$2.15 26.04,55.56 v27.94,55.56
  Bottom 0.254: v8.57,68.58 11.75,65.41 v22.86,65.41 | v23.81,56.83 v22.54,58.1 | v15.88,55.88 16.19,55.56 v22.54,55.56 | IC1.6 33.34,54.29 30.16,54.29 28.89,55.56 v27.94,55.56
D5_A5  (via drill 0.61)
  Top 0.254: v11.11,56.2 11.11,56.83 12.7,56.83 U$1.16 | v3.81,59.69 v3.81,56.52 4.13,56.2 v4.13,50.16 | v4.13,61.59 4.13,66.04 5.08,66.99 5.4,66.99 U$1.3 | v28.89,54.29 28.89,56.83 26.04,56.83 U$2.16 | v28.26,51.44 28.57,51.12 28.57,46.35 IC1.11
  Bottom 0.254: v11.11,56.2 10.79,56.52 v3.81,56.52 | v3.81,59.69 3.81,61.59 v4.13,61.59 | v28.89,54.29 28.89,52.07 v28.26,51.44 27.62,51.44 26.35,49.85 24.77,49.85 24.13,49.21 19.68,49.21 19.37,48.9 5.4,48.9 v4.13,50.16
D6_A6  (via drill 0.61)
  Top 0.254: v10.79,68.26 10.79,58.1 12.7,58.1 U$1.17 13.02,58.1 14.92,58.1 15.24,57.78 v15.88,57.78 | v14.61,68.26 13.34,66.99 13.02,66.99 U$1.24 | v22.54,56.83 23.5,57.78 23.5,58.1 25.72,58.1 U$2.17 | IC1.12 30.48,38.73 30.16,39.05 22.54,39.05 v22.54,50.8
  Bottom 0.254: v10.79,68.26 v14.61,68.26 | v15.88,57.78 21.59,57.78 v22.54,56.83 23.5,55.88 23.5,55.24 22.86,54.61 22.54,54.61 v22.54,50.8
D7_A7  (via drill 0.61)
  Top 0.254: U$1.25 12.7,68.26 12.06,68.26 11.43,67.63 11.43,59.37 12.7,59.37 U$1.18 13.02,59.37 13.02,59.69 v15.24,59.69 | v23.5,59.37 25.72,59.37 U$2.18 | v37.78,36.83 38.42,37.78 v38.42,46.35 | v37.78,51.44 35.56,53.66 35.56,56.83 34.61,57.78 31.43,57.78 v31.43,58.42
  Bottom 0.254: v15.24,59.69 23.18,59.69 v23.5,59.37 24.45,58.42 v31.43,58.42 | IC1.13 33.97,36.83 v37.78,36.83 | v38.42,46.35 37.47,47.31 37.47,51.44 v37.78,51.44
G
  Top 0.254: R10.2 15.24,123.83 R10.2 | 14.29,124.14 14.61,123.83 R10.2
  Top 0.406: 14.29,124.14 14.29,125.41 X3.2
GND  (via drill 0.61)
  Top 0.254: IC3.26 47.62,18.1 46.99,18.1 IC3.25 46.99,17.78 47.04,17.14 | IC3.18 42.49,18.09 | 44.45,18.1 IC3.21 44.45,17.78 | 45.09,25.08 IC3.7 | CON1.GND1 7.3,1.91 16.51,1.91 33.97,1.91 33.97,4.13 CON1.GND | v11.11,54.29 12.7,54.29 U$1.14 | v27.62,54.29 26.04,54.29 U$2.14 25.72,54.29 v24.13,54.29 | v14.61,69.53 13.02,69.53 U$1.26 | v27.94,69.22 26.04,69.53 U$2.26 | v29.84,56.52 29.53,56.83 29.53,58.1 28.57,59.05 v28.57,60.33 | v31.43,60.33 31.11,60.64 31.11,60.96 29.84,62.23 C6.1 | JP5.1 53.98,63.18 53.98,64.14 S1.1 | 27.3,114.94 C25.1 | 27.3,114.94 27.3,114.62 IC7.12 27.3,114.94 | C25.1 | 27.3,114.94 27.3,115.89 IC7.13 | JP13.1 7.62,81.6 5.08,84.14 5.08,107 C2.1 | IC4.22 19.05,106.05 16.83,108.27 IC10.1 | v22.86,109.54 21.27,109.54 IC7.7 | 7.62,113.35 7.62,110.81 10.48,110.81 IC10.14 | 7.62,113.35 7.3,113.67 S2.2 7.62,113.35 | 7.62,113.35 10.48,113.35 IC10.12 10.79,113.35 11.43,113.35 12.06,113.98 12.06,116.84 12.38,117.16 12.7,117.16 16.51,117.16 IC10.8 | C25.1 v30.16,113.35 | 37.15,16.51 X1.S1 37.15,16.51
  Top 0.406: 42.49,18.09 42.49,19.04 42.86,19.68 44.45,19.68 | 44.45,19.68 44.45,18.1 | 45.09,25.08 45.09,23.18 45.09,21.27 45.09,20.32 44.45,19.68 | 47.04,16.51 47.04,17.14 | 47.04,16.51 44.45,16.51 44.45,17.78 | 47.04,16.51 v50.16,16.51 47.04,16.51
  Top 0.61: 16.51,32.07 18.1,32.08 18.22,32.08 CON1.P3B | CON1.P3A 16.51,32.07 | QG1.7 17.14,39.69 16.51,39.05 16.51,34.92 16.51,32.7 16.51,32.07 | C4.1 13.65,51.44 v16.51,53.98 | v38.42,57.78 39.05,56.83 39.05,53.34 IC1.22 | C23.2 C26.2
  Top 0.813: R1.2 37.15,16.51 37.15,6.99 37.15,5.71 37.15,5.4 36.2,4.45 CON1.GND
  Bottom 0.254: v28.57,60.33 v31.43,60.33 36.2,60.33 38.42,58.1 v38.42,57.78
  Bottom 0.813: JP6.1 JP13.1
  pour Bottom (isolate 0.254): 0,139.38 63.5,139.38 63.5,0 0,0
HSYNC  (via drill 0.61)
  Top 0.254: IC4.15 36.83,103.82 36.83,110.17 34.92,111.12 34.92,113.98 40.96,120.02 v40.96,120.97 | v36.83,123.19 28.89,123.19 23.5,127.95 23.5,130.49 22.23,131.76 21.27,131.76 16.83,131.76 16.51,131.44 16.51,130.49 X3.13
  Bottom 0.254: v40.96,120.97 40.96,123.19 v36.83,123.19
MISO_A9  (via drill 0.61)
  Top 0.254: v14.29,62.23 14.29,63.18 13.02,63.18 U$1.21 | v9.84,62.55 8.89,63.5 v8.89,64.14 | 26.67,30.16 CON1.P7 | v26.35,61.91 26.35,62.87 26.04,63.18 U$2.21 | SV1.1 60.64,27.3 v60.64,41.59 | v33.02,27.62 28.57,27.62 27.3,28.89 27.3,29.53 26.99,29.84 CON1.P7 | v38.1,30.16 38.73,30.16 39.37,30.8 39.37,40.32 39.37,40.64 40.01,41.27 IC1.18 | v26.67,33.02 26.67,31.43 26.67,30.16 | 26.67,30.16 CON1.P7
  Bottom 0.254: v14.29,62.23 13.97,62.55 v9.84,62.55 | v8.89,64.14 7.3,62.55 2.86,62.55 2.22,61.91 2.22,40.96 14.29,40.96 14.61,40.96 14.92,40.64 14.92,33.34 15.24,33.02 v26.67,33.02 | v26.35,61.91 27.3,62.87 34.61,62.87 39.37,58.1 39.37,55.24 42.23,55.24 44.77,52.7 45.09,52.7 46.04,51.75 46.04,41.91 | 46.04,41.91 46.04,41.59 41.59,41.59 IC1.18 | v60.64,41.59 60.33,41.91 46.04,41.91 | v33.02,27.62 v38.1,30.16
MOSI_A8  (via drill 0.61)
  Top 0.254: v15.24,63.18 15.24,60.64 13.02,60.64 U$1.19 | v23.5,62.87 25.72,60.64 U$2.19 | v44.77,30.16 43.81,30.16 43.18,30.8 43.18,38.1 42.55,38.73 IC1.17 | v16.83,20 13.97,22.86 13.97,34.61 13.97,40.64 14.61,41.27 16.51,41.27 | 16.51,41.27 v18.1,41.27 16.51,41.27 | 16.51,41.27 v16.51,50.16
  Bottom 0.254: v23.5,62.87 15.56,62.87 v15.24,63.18 14.92,63.5 9.53,63.5 2.86,56.83 2.86,52.7 4.13,52.7 6.67,50.16 9.21,50.16 9.53,50.16 9.84,49.85 16.19,49.85 v16.51,50.16 | 15.24,20 15.24,18.73 IC2.4 | 15.24,20 IC2.5 15.24,20 | 15.24,20 v16.83,20 | v18.1,41.27 19.37,42.55 21.91,42.55 22.23,42.23 29.84,42.23 30.16,42.55 36.51,42.55 40.32,38.73 IC1.17 | SV1.4 53.66,24.77 48.9,24.77 v44.77,30.16
MOSI_MMC  (via drill 0.61)
  Top 0.254: v16.83,21.59 15.56,22.86 14.92,23.5 14.92,29.84 CON1.P2
  Bottom 0.254: v16.83,21.59 16.51,21.27 15.24,21.27 IC2.6
N$1
  Top 0.254: R1.1 40.64,25.4 IC3.14
N$2
  Top 0.254: LED3.A 46.35,124.78 R7.1
N$3
  Top 0.254: IC1.21 C7.1
N$4
  Bottom 0.254: JP2.2 32.7,46.04 IC1.9
N$5
  Bottom 0.254: IC4.21 C14.1
N$6
  Bottom 0.254: IC4.8 C1.2
N$7
  Top 0.254: LED1.A R2.1
N$8  (via drill 0.61)
  Top 0.254: IC3.23 45.72,18.1 45.72,18.73 46.04,19.05 v46.04,20.32 | v36.2,21.91 35.56,22.54 35.56,39.05 34.61,40.01 31.11,40.01 31.11,40.64 27.94,43.5 JP2.1
  Bottom 0.254: v46.04,20.32 46.04,21.91 v36.2,21.91
N$9
  Top 0.254: IC3.16 41.27,17.78 41.27,15.88 42.23,14.92 X1.2
N$10
  Top 0.254: IC3.15 40.64,17.78 40.64,14.61 42.23,13.02 X1.3
N$11
  Top 0.254: IC4.23 15.24,104.78 15.24,109.54 16.51,109.54 IC10.2
N$12  (via drill 0.61)
  Top 0.254: v12.38,25.72 10.16,27.94 10.16,30.8 6.99,33.97 LED2.K
  Bottom 0.254: v12.38,25.72 17.78,25.72 20.95,22.54 IC2.8
N$13
  Top 0.254: R6.1 3.49,31.75 LED2.A
N$14
  Top 0.254: C3.2 IC1.8
N$15
  Bottom 0.406: JP10.3 48.9,107 QG2.8
N$16
  Top 0.254: IC4.24 13.97,110.49 14.29,110.81 16.51,110.81 IC10.3
N$17
  Top 0.254: IC4.25 12.7,104.78 12.7,111.12 13.02,111.44 14.29,111.44 14.61,111.76 14.61,112.08 16.51,112.08 IC10.4
N$18  (via drill 0.61)
  Top 0.254: v12.7,113.03 12.7,113.67 14.29,113.67 14.61,113.35 16.51,113.35 IC10.5
  Bottom 0.254: v12.7,113.03 9.21,109.54 9.21,103.5 IC4.26
N$19  (via drill 0.61)
  Top 0.254: v6.03,106.68 6.35,106.36 IC4.27 | v6.99,110.17 6.99,111.44 5.71,112.71 5.71,115.25 5.71,115.57 6.03,115.89 10.48,115.89 IC10.10
  Bottom 0.254: v6.03,106.68 v6.99,110.17
N$20  (via drill 0.61)
  Top 0.254: v8.57,114.3 8.57,114.62 10.48,114.62 | 10.48,114.62 IC10.11 10.48,114.62
  Bottom 0.254: v8.57,114.3 8.57,112.08 8.26,111.76 4.13,111.76 3.81,111.44 3.81,106.05 3.81,105.41 3.81,103.82 IC4.28
N$21  (via drill 0.61)
  Top 0.254: v14.92,114.62 16.51,114.62 IC10.6 | v33.97,106.36 35.56,104.78 35.56,97.79 36.83,96.52 IC4.14
  Bottom 0.254: v14.92,114.62 15.24,114.94 28.26,114.94 28.57,114.62 28.57,112.08 28.89,111.76 29.84,111.76 30.16,111.44 30.16,111.12 30.16,108.27 30.16,107.95 30.48,107.63 33.66,107.63 33.97,107.31 v33.97,106.36
N$22  (via drill 0.61)
  Top 0.254: v11.75,107 12.06,107.31 12.06,109.54 10.79,109.54 IC10.15
  Bottom 0.254: v11.75,107 15.24,110.49 26.35,110.49 26.99,109.86 26.99,106.68 26.99,106.36 26.99,106.05 27.3,105.73 33.02,105.73 33.97,105.09 33.97,103.82 IC4.16
N$23  (via drill 0.3, 0.6 pad 0.41)
  Top 0.152: 49.85,44.13 Q1.1
  Top 0.305: IC1.10 35.56,43.81 36.2,44.45 36.2,46.99 36.83,47.62 37.47,47.62 38.42,47.62 39.05,46.99 39.37,46.67 39.37,43.18 40.01,42.55 42.23,42.55 43.81,41.91 44.13,41.59 v44.13,36.83 | C26.1 49.85,44.13 48.9,43.5 48.9,36.83 v49.53,36.2
  Bottom 0.305: v44.13,36.83 44.77,36.2 v49.53,36.2
N$24
  Top 0.305: Q1.2 49.85,38.42 51.75,36.51 53.34,36.51 C23.1
N$25  (via drill 0.61)
  Top 0.254: v25.4,113.67 25.4,119.06 25.08,119.38 20.64,119.38 19.37,120.02 19.37,120.65 17.46,120.65 R11.1 | v28.89,110.17 28.26,109.54 27.3,109.54 IC7.8
  Bottom 0.254: v28.89,110.17 v25.4,113.67
N$26  (via drill 0.61)
  Top 0.254: v13.97,112.71 13.97,112.08 10.79,112.08 IC10.13 | v18.41,112.71 19.68,112.71 20.32,113.35 20.95,113.35 IC7.4 21.27,113.35 21.91,113.35 22.23,113.67 | 22.23,113.67 22.54,113.98 22.54,117.16 21.27,117.16 IC7.1 | 22.23,113.67 23.81,112.08 23.81,110.81 26.99,110.81 IC7.9
  Bottom 0.254: v13.97,112.71 v18.41,112.71
N$27
  Top 0.254: IC4.13 30.48,99.69 30.48,112.08 27.3,112.08 IC7.10
N$28
  Top 0.254: IC4.12 27.94,99.69 27.94,106.05 22.54,106.05 19.68,108.9 19.68,112.08 20.95,112.08 IC7.5
N$29  (via drill 0.61)
  Top 0.254: v19.68,118.75 19.68,115.89 20.95,115.89 IC7.2 | v31.75,115.57 33.02,114.3 33.02,99.38 35.56,96.84 35.56,94.93 34.61,93.98 29.21,93.98 IC4.11
  Bottom 0.254: v19.68,118.75 22.54,115.89 31.43,115.89 v31.75,115.57
N$30
  Top 0.254: R9.1 11.75,120.65 14.29,118.11 18.73,118.11 19.05,117.79 19.05,115.57 20,114.62 20.95,114.62 IC7.3
N$31  (via drill 0.61)
  Top 0.254: v20.95,120.33 20.95,121.6 20.64,121.92 15.88,121.92 14.61,120.97 R10.1 | v22.86,118.43 24.45,116.84 24.45,112.08 v24.77,111.76 | v22.86,111.44 22.23,110.81 21.27,110.81 IC7.6
  Bottom 0.254: v22.86,118.43 v20.95,120.33 | v24.77,111.76 24.45,111.44 v22.86,111.44
N$35  (via drill 0.61)
  Top 0.254: v42.86,120.97 42.86,119.06 R12.1 | IC4.4 7.62,99.69 7.62,106.36 4.76,109.22 3.81,109.22 3.81,124.14 12.06,132.4 35.24,132.4 38.1,129.54 43.18,129.54 43.81,130.81 X2.1
  Bottom 0.254: v42.86,120.97 43.81,122.87 43.81,130.81 X2.1
N$36
  Top 0.254: R13.1 39.05,124.78 41.59,127.32 41.59,128.27 X2.5 41.91,128.59 43.18,128.59 45.09,130.49 45.09,132.4 48.9,132.4 51.44,129.54 51.44,121.92 47.62,118.11 47.62,108.27 40.96,101.6 40.96,89.85 14.92,89.85 13.97,90.81 IC4.5
N$37
  Top 0.813: B1.AC1 57.78,123.51 57.78,125.73 J1.1
N$38
  Top 0.813: B1.AC2 55.24,123.83 55.24,129.22 57.78,131.76 J1.3
N$39
  Top 0.61: C18.+ 50.16,115.89
  Top 0.813: 50.16,115.89 B1.+
  Bottom 0.254: C19.2 38.73,111.76 IC8.1 38.73,112.08
  Bottom 0.813: 38.73,112.08 40.01,113.35 46.35,113.35 48.9,115.89 49.53,116.2 C18.+
N$40  (via drill 0.6)
  Top 0.813: JP11.1 38.42,91.76 39.37,92.71 39.37,111.44 38.73,112.08 v35.88,112.08
  Bottom 0.254: C20.2 33.66,112.08 IC8.3
  Bottom 0.61: v35.88,112.08 33.95,112.08 IC8.3
R
  Top 0.254: 12.06,124.14 11.75,123.83 R9.2 | R9.2 12.06,124.14 | R9.2 12.06,124.14
  Top 0.406: 12.06,124.14 12.06,125.41 X3.1
RESET_CPM  (via drill 0.61)
  Top 0.254: IC1.1 C6.2 | JP9.2 53.98,69.22 53.98,68.9 S1.3 53.66,68.58 47.62,68.58 S1.4 | v51.44,32.07 48.26,35.24 48.26,53.02 R4.2
  Bottom 0.254: R4.2 51.12,55.88 51.12,68.26 53.34,68.26 53.66,68.58 S1.3 | IC1.1 33.66,67.94 37.47,67.94 46.04,67.94 46.67,68.58 47.31,68.58 S1.4 | SV1.5 57.15,32.07 v51.44,32.07
RESET_VGA
  Top 0.254: C2.2 2.54,110.81 | C2.2 | 2.54,110.81 R8.2 2.54,110.81 | IC4.1 2.54,97.16 C2.2 | 2.54,110.81 2.54,113.67 S2.4 2.54,113.98 2.54,120.33 S2.3
RXD_AVR  (via drill 0.61)
  Top 0.254: v55.24,39.37 v55.24,44.45
  Bottom 0.254: IC1.14 36.2,33.66 37.47,34.92 40.01,37.47 52.07,37.47 52.7,38.1 54.61,38.1 v55.24,39.37 | v55.24,44.45 55.56,44.45 58.1,44.45 JP4.4
RXD_FTDI  (via drill 0.61)
  Top 0.254: IC3.5 46.35,25.4 46.35,26.04 45.72,26.99 45.72,32.07 | 45.72,32.07 45.72,31.75 45.72,32.07 | 45.72,32.07 45.72,39.69 v45.72,40.32 | JP8.3 JP4.1 58.1,45.09 58.1,47.31 57.78,47.62 56.83,47.62 56.2,48.26 56.2,49.21 56.2,53.34 56.2,53.98 56.83,54.61 JP3.3
  Bottom 0.254: v45.72,40.32 46.04,40.64 JP8.3
RXD_VGA
  Top 0.254: IC4.2 6.35,85.09 6.99,84.45 10.48,84.45 17.14,84.45 17.78,83.82 JP13.5
  Bottom 0.254: JP8.2 61.91,40.96 61.91,58.74 61.59,59.05 57.78,59.05 56.2,60.64 56.2,70.17 46.67,70.17 46.35,70.8 20.95,70.8 19.37,68.9 16.51,68.9 15.56,69.85 15.56,71.75 16.51,71.75 17.78,73.03 JP6.5
  Bottom 0.813: JP6.5 JP13.5
SCK_A10  (via drill 0.61)
  Top 0.254: v8.57,60.64 5.71,60.64 U$1.8 5.4,60.64 2.54,60.64 2.54,46.04 5.4,44.77 5.4,34.92 4.76,34.29 4.76,32.07 6.35,30.48 v6.35,19.05 | v17.46,61.91 18.41,60.96 18.41,60.64 U$2.8 | IC1.19 44.77,42.23 v44.77,32.07
  Bottom 0.254: v8.57,60.64 9.53,61.59 13.65,61.59 13.97,61.28 15.56,61.28 16.19,61.91 v17.46,61.91 | 21.27,16.19 24.45,16.19 R5.1 24.77,16.19 34.61,26.04 37.15,26.04 43.18,32.07 v44.77,32.07 46.35,30.48 53.66,30.48 54.29,29.21 57.47,29.21 SV1.3 | IC2.13 21.27,16.19 | 21.27,16.19 21.27,17.46 IC2.12 | IC2.13 21.27,16.19 | v6.35,19.05 11.43,13.97 17.14,13.97 19.37,16.19 20.95,16.19 IC2.13
SCK_MMC  (via drill 0.61)
  Top 0.254: v23.18,19.37 23.18,29.84 CON1.P5
  Bottom 0.254: v23.18,19.37 22.54,18.73 21.27,18.73 IC2.11
SCL
  Top 0.254: IC1.28 41.27,71.12 43.18,72.39 JP6.15
SDA
  Top 0.254: IC1.27 39.37,65.72 39.37,71.12 40.64,72.39 JP6.14
TXD_AVR
  Bottom 0.254: IC1.15 41.27,34.92 53.66,34.92 JP8.4
TXD_FTDI  (via drill 0.61)
  Top 0.254: v50.8,26.04 49.53,26.04 48.9,25.4 IC3.1 | v50.8,29.53 53.34,29.53 53.98,30.16 53.98,33.34 54.61,33.97 57.47,33.97 58.1,34.61 58.1,37.47 58.1,38.42 58.1,39.37 58.1,40.01 59.05,40.64 | 59.05,40.64 JP8.1 | JP8.1 JP4.3 | 59.05,40.64 JP8.1
  Bottom 0.254: v50.8,26.04 v50.8,29.53 | JP3.2 61.28,49.85 61.28,43.18 JP4.3
TXD_VGA  (via drill 0.61)
  Top 0.254: v43.18,55.56 43.18,59.37 42.23,60.33 37.78,60.33 37.78,65.72 32.07,71.44 20.32,71.44 JP6.6 | IC4.3 8.89,86.36 9.53,85.72 19.68,85.72 20.32,85.09 JP13.6
  Bottom 0.254: JP4.2 53.02,49.53 49.21,49.53 v43.18,55.56
  Bottom 0.813: JP13.6 JP6.6
VSYNC  (via drill 0.61)
  Top 0.254: IC4.17 v31.75,114.3 | v31.43,119.38 21.59,127.95 20.95,128.59 19.05,130.49 18.73,130.49 X3.14
  Bottom 0.254: v31.75,114.3 32.7,115.25 32.7,117.79 v31.43,119.38

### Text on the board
Top: Top | AVR VGA | V 1.0 | 1 | Rx VGA | Tx VGA | CLK | 1 | Rx VGA | Tx VGA | SDA | SCL | CLK | Reset | Reset | GND | + | GND | Rx | Tx | GND | JP4 | JP8 | + | + | V 2.0 | 3.3V | Top | 5V | AVR CP/M | +
Bottom: Bottom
